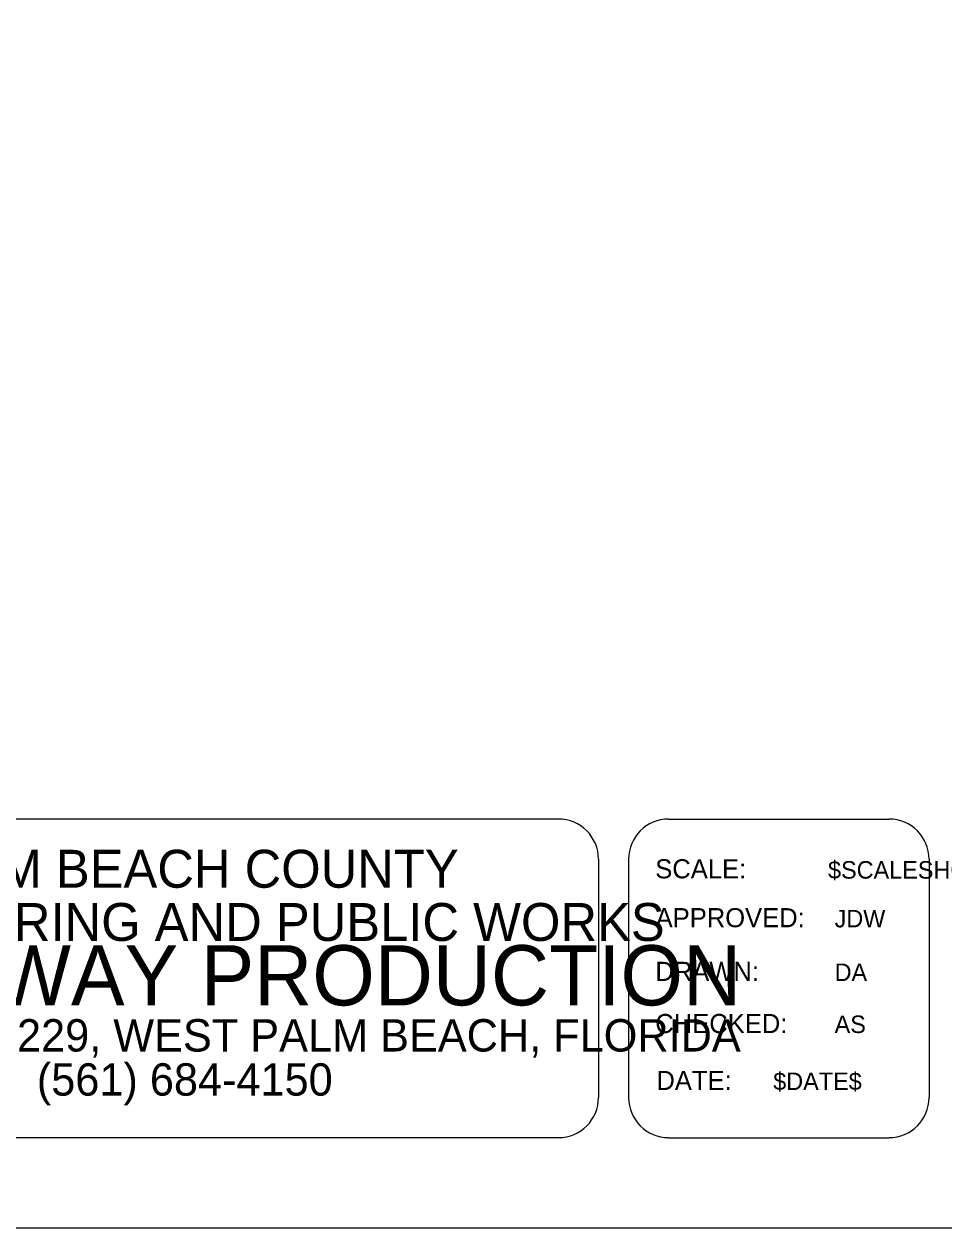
# Model space of a CAD drawing. Extents: x -0.7 to 16, y -0.9 to 9.7.
# Drawn here: x 9.999 to 12.024, y -0.9 to 1.75 of the extents above; entities that cross this region are included whole.
import ezdxf

# ---------------------------------------------------------------- set-up
doc = ezdxf.new("R2010")
doc.units = 0
doc.layers.add('Default', color=7, linetype='Continuous')
doc.layers.add('PlotBorder_dp', color=7, linetype='Continuous')

msp = doc.modelspace()

# ---------------------------------------------------------------- linework, layer by layer
at = {"layer": 'Default'}
for p, q in [((11.1756, 0), (8.7497, 0)), ((11.4182, 0), (11.9034, 0)), ((11.2638, -0.0882), (11.2638, -0.6131)), ((11.33, -0.0882), (11.33, -0.6131)), ((11.9916, -0.0882), (11.9916, -0.6131)), ((11.1756, -0.7014), (8.7497, -0.7014)), ((11.4182, -0.7014), (11.9034, -0.7014))]:
    msp.add_line(p, q, dxfattribs=at)
for centre, major_axis, start_param, end_param in [((11.1756, -0.0882), (0, 0.0882), 4.712389, 6.283185), ((11.4182, -0.0882), (0, 0.0882), 0, 1.570796), ((11.9034, -0.0882), (0, 0.0882), 4.712389, 6.283185), ((11.1756, -0.6131), (0, 0.0882), 3.141593, 4.712389), ((11.4182, -0.6131), (0, -0.0882), 4.712389, 6.283185), ((11.9034, -0.6131), (0, -0.0882), 0, 1.570796)]:
    msp.add_ellipse(centre, major_axis=major_axis, ratio=0.999927, start_param=start_param, end_param=end_param, dxfattribs=at)
at = {"layer": 'PlotBorder_dp'}
msp.add_lwpolyline([(-0.55, -0.9), (15.95, -0.9), (15.95, 9.7), (-0.55, 9.7)], close=True, dxfattribs=at)

# ---------------------------------------------------------------- texts
at = {"layer": 'Default'}
for s, height, p in [('PALM BEACH COUNTY', 0.083446, (9.7345, -0.1511)), ('ENGINEERING AND PUBLIC WORKS', 0.083468, (9.4745, -0.2683)), ('ROADWAY PRODUCTION', 0.132369, (9.4241, -0.4101)), ('P.O. BOX 21229, WEST PALM BEACH, FLORIDA', 0.071224, (9.4333, -0.5117)), ('(561) 684-4150', 0.071224, (10.0274, -0.6088))]:
    msp.add_text(s, height=height, rotation=360, dxfattribs=at).set_placement(p)
for s, height, p in [('SCALE:', 0.04207, (11.3888, -0.1305)), ('$SCALESHORT$', 0.038546, (11.7691, -0.1311)), ('APPROVED:', 0.04207, (11.3896, -0.2381)), ('JDW', 0.03855, (11.7836, -0.2384)), ('DRAWN:', 0.04207, (11.389, -0.3563)), ('DA ', 0.03855, (11.7836, -0.3565)), ('CHECKED:', 0.04207, (11.3889, -0.4711)), ('AS', 0.03855, (11.7836, -0.471)), ('DATE:', 0.04207, (11.3913, -0.5963)), ('$DATE$', 0.03855, (11.6484, -0.5965))]:
    msp.add_text(s, height=height, dxfattribs=at).set_placement(p)

doc.saveas('drawing.dxf')
